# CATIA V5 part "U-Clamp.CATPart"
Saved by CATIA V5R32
Part number: U-Clamp
Bounding box of the stored display mesh (mm): x -23 to 23, y -6.5 to 6.5, z -25 to 29
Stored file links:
  D:\PROJECTS\Project 2022\CATIA V5 6R 2022\Resources\Tutorial Files\c14_catia_v5_6r2022_tut\c14tut2\c14tut2.CATParts\U-Clamp.CATPart
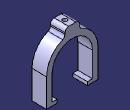
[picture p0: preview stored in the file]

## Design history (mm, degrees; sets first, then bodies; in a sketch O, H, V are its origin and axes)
Body1 (main body)
  Sketch1 on zx-plane, origin (0, 0, 0), H (-1, 0, 0), V (0, 0, 1)
    arc A1 centre (0, 0) radius 18 from (18, 0) to (-18, 0) ccw
    point P1 (-18, 0)
    point P2 (18, 0)
    line L1 (-18, 0) -> (-18, -22)
    point P3 (-18, -22)
    line L2 (-18, -22) -> (-13.5, -22)
    point P4 (-13.5, -22)
    line L3 (-13.5, -22) -> (-13.5, -25)
    point P5 (-13.5, -25)
    line L4 (-13.5, -25) -> (-23, -25)
    point P6 (-23, -25)
    line L5 (-23, -25) -> (-23, 0)
    point P7 (-23, 0)
    arc A2 centre (0, 0) radius 23 from (-23, 0) to (-6.5, 22.0624) cw
    point P9 (23, 0)
    point P10 (23, 0)
    point P11 (23, -25)
    line L6 (23, -25) -> (23, 0)
    point P12 (13.5, -25)
    line L7 (13.5, -25) -> (23, -25)
    point P13 (13.5, -22)
    line L8 (13.5, -22) -> (13.5, -25)
    point P14 (18, -22)
    line L9 (18, -22) -> (13.5, -22)
    point P15 (18, 0)
    line L10 (18, 0) -> (18, -22)
    line L11 (-6.5, 22.0624) -> (-6.5, 29)
    point P16 (-6.5, 29)
    line L12 (-6.5, 29) -> (6.5, 29)
    point P17 (6.5, 29)
    line L13 (6.5, 29) -> (6.5, 22.0624)
    point P18 (6.5, 22.0624)
    arc A3 centre (0, 0) radius 23 from (6.5, 22.0624) to (23, 0) cw
    distance L3 V = 13.5
    distance H L4 = 25
    distance V L5 = 23
    distance P16 P17 = 13
    distance L11 V = 6.5
    distance L7 L12 = 54
    distance L1 L5 = 5
    length L3 = 3
    coincidence: P1 H, P2 H, P7 H, A2 P18, A2 A3, P2 P15, P9 P10
    tangency: L1 A1, A2 L5
    horizontal: L2 H, L4 H, L12 H
    vertical: L3 V, L5 V, L11 V, L13 V
    concentricity: A2 A1
    symmetry: P7 P10 V, P6 P11 V, L5 L6 V, P5 P12 V, L4 L7 V, P4 P13 V, L3 L8 V, P3 P14 V, L2 L9 V, P1 P15 V, L1 L10 V
  Pad1: profile Sketch1, direction (0, -1, 0), length 6.5, mirrored extent
  Fillet1: radius 3.302, on 4 edges
  Sketch2 on face of Pad1, origin (-0.057, 2.6412, 29), H (1, 0, 0), V (0, 1, 0)
    point P1 (0.057, -2.6412)
    reference intersected line E1 through (0.057, 0) direction (0, 1) from yz-plane
    reference intersected line E2 through (0, -2.6412) direction (-1, 0) from zx-plane
    coincidence: E1 P1, E2 P1
  Hole1: placed by Sketch2, at (0, 0, 29) direction (0, 0, -1), diameter 4, depth 25.4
